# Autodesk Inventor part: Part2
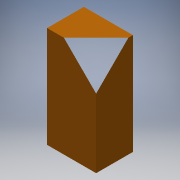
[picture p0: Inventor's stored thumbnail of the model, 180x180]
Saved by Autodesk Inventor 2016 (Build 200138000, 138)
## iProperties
Created: 2020-04
Part Number: Part2
Material: Generic
Document SubType Name: Modeling
Designer: merlin
Density: 1 g/cm^3
Appearance: Orange
Author: merlin
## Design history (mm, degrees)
sketch "Sketch1"
  geometry: L1 (-22.225, 19.05)-(-74.612, 19.05); L2 (-74.612, 19.05)-(-74.612, 38.1); L3 (-74.612, 38.1)-(-22.225, 38.1); L4 (-22.225, 38.1)-(-22.225, 19.05); 1 further point
  constraints: 8 end point, 2 parallel, 1 horizontal, 1 perpendicular
extrude "Extrusion1" new body sketch "Sketch1" distance "d0" = 25.4; taper "d1" = 0 deg
body "Solid1"
